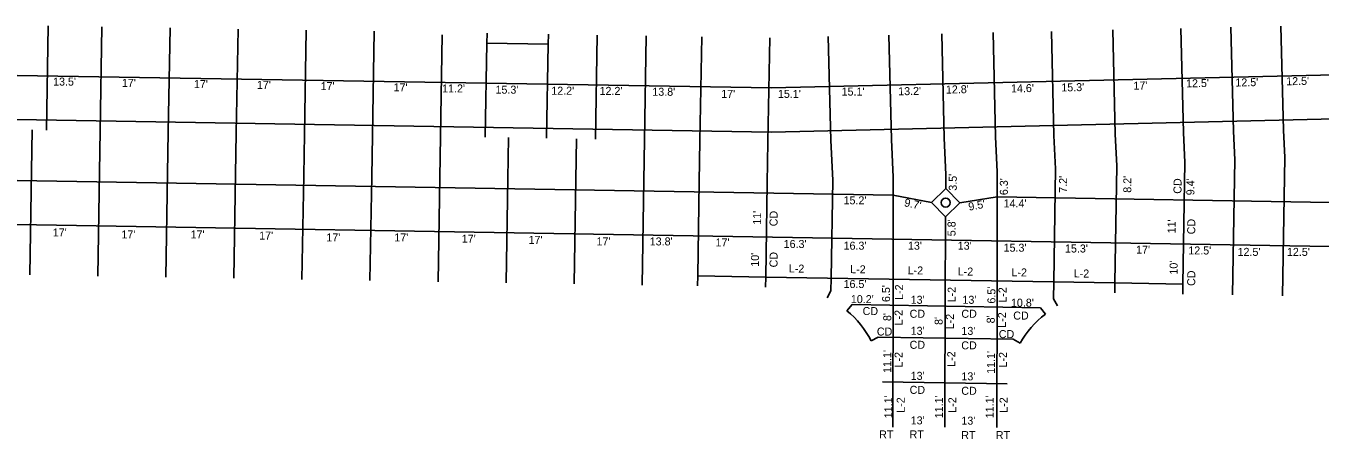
# Model space of a CAD drawing. Extents: x 4995357 to 4999033, y 3881202 to 3881750.
# Drawn here: x 4996458 to 4996781.3, y 3881601.9 to 3881705.1 of the extents above; entities that cross this region are included whole.
import ezdxf

# ---------------------------------------------------------------- set-up
doc = ezdxf.new("R2010")
doc.units = 0
for name, color, linetype in [('dsn3DCenterLine', 7, 'Continuous'), ('dsn3DCurbFormgrade', 7, 'Continuous'), ('dsn3DCurbTop', 7, 'Continuous'), ('dsn3DDNC', 7, 'Continuous'), ('dsn3DExistingPvmtBtm', 7, 'Continuous'), ('dsn3DIntakeWell', 7, 'Continuous')]:
    doc.layers.add(name, color=color, linetype=linetype)

msp = doc.modelspace()

# ---------------------------------------------------------------- linework, layer by layer
at = {"layer": 'dsn3DCurbFormgrade'}
for p, q in [((4996463.52, 3881705.11), (4996463.09, 3881679.11)), ((4996771.53, 3881705.08), (4996772.14, 3881679.09)), ((4996476.98, 3881704.89), (4996476.54, 3881678.89)), ((4996493.97, 3881704.6), (4996493.54, 3881678.61)), ((4996510.97, 3881704.32), (4996510.54, 3881678.33)), ((4996527.97, 3881704.04), (4996527.54, 3881678.04)), ((4996544.97, 3881703.76), (4996544.53, 3881677.76)), ((4996561.95, 3881702.85), (4996561.53, 3881677.48)), ((4996600.3, 3881676.83), (4996600.73, 3881702.83)), ((4996612.96, 3881702.63), (4996612.52, 3881676.63)), ((4996626.8, 3881702.4), (4996626.37, 3881676.4)), ((4996643.8, 3881702.12), (4996643.37, 3881676.12)), ((4996658.44, 3881702.44), (4996659.05, 3881676.45)), ((4996673.58, 3881702.77), (4996674.19, 3881676.78)), ((4996686.79, 3881703.1), (4996687.4, 3881677.11)), ((4996699.62, 3881703.43), (4996700.23, 3881677.44)), ((4996714.19, 3881703.74), (4996714.8, 3881677.75)), ((4996729.51, 3881704.1), (4996730.12, 3881678.11)), ((4996746.55, 3881704.5), (4996747.16, 3881678.51)), ((4996759.04, 3881704.79), (4996759.65, 3881678.8)), ((4996572.74, 3881677.29), (4996573.13, 3881700.79)), ((4996588.07, 3881677.04), (4996588.46, 3881700.53)), ((4996715.22, 3881669.4), (4996714.75, 3881641.18)), ((4996730.52, 3881670.16), (4996730.03, 3881640.92)), ((4996747.53, 3881671.01), (4996747.03, 3881640.64)), ((4996759.45, 3881637.94), (4996760.01, 3881671.64)), ((4996771.91, 3881637.73), (4996772.48, 3881672.26)), ((4996459.38, 3881668.92), (4996458.94, 3881642.93)), ((4996476.37, 3881668.64), (4996475.94, 3881642.65)), ((4996493.37, 3881668.36), (4996492.94, 3881642.36)), ((4996510.37, 3881668.08), (4996509.94, 3881642.08)), ((4996527.37, 3881667.79), (4996526.93, 3881641.8)), ((4996544.36, 3881667.51), (4996543.93, 3881641.52)), ((4996561.36, 3881667.23), (4996560.93, 3881641.23)), ((4996578.36, 3881666.95), (4996577.93, 3881640.95)), ((4996595.36, 3881666.66), (4996594.92, 3881640.67)), ((4996612.35, 3881666.38), (4996611.92, 3881640.39)), ((4996626.2, 3881666.15), (4996625.81, 3881642.66)), ((4996659.54, 3881666.61), (4996659.13, 3881642.1)), ((4996674.66, 3881667.37), (4996674.61, 3881641.85)), ((4996687.82, 3881664.51), (4996687.81, 3881668.03)), ((4996700.66, 3881668.67), (4996700.61, 3881641.41)), ((4996643.2, 3881665.87), (4996642.81, 3881642.37)), ((4996687.68, 3881651.63), (4996687.7, 3881657.44)), ((4996687.61, 3881641.63), (4996687.68, 3881651.63)), ((4996664.37, 3881635.51), (4996711.43, 3881634.73)), ((4996670.93, 3881627.4), (4996704.6, 3881626.84)), ((4996672.01, 3881616.25), (4996703.15, 3881615.74))]:
    msp.add_line(p, q, dxfattribs=at)
at = {"layer": 'dsn3DCurbTop'}
for p, q in [((4996459.38, 3881668.92), (4996459.55, 3881679.17)), ((4996772.48, 3881672.26), (4996772.14, 3881679.09)), ((4996476.37, 3881668.64), (4996476.54, 3881678.89)), ((4996493.37, 3881668.36), (4996493.54, 3881678.61)), ((4996510.54, 3881678.33), (4996510.37, 3881668.08)), ((4996527.37, 3881667.79), (4996527.54, 3881678.04)), ((4996544.53, 3881677.76), (4996544.36, 3881667.51)), ((4996561.36, 3881667.23), (4996561.53, 3881677.48)), ((4996578.36, 3881666.95), (4996578.53, 3881677.2)), ((4996595.36, 3881666.66), (4996595.53, 3881676.91)), ((4996612.35, 3881666.38), (4996612.52, 3881676.63)), ((4996626.37, 3881676.4), (4996626.2, 3881666.15)), ((4996643.2, 3881665.87), (4996643.37, 3881676.12)), ((4996659.54, 3881666.61), (4996659.05, 3881676.45)), ((4996674.66, 3881667.37), (4996674.19, 3881676.78)), ((4996687.81, 3881668.03), (4996687.4, 3881677.11)), ((4996700.66, 3881668.67), (4996700.23, 3881677.44)), ((4996715.22, 3881669.4), (4996714.8, 3881677.75)), ((4996730.52, 3881670.16), (4996730.12, 3881678.11)), ((4996747.53, 3881671.01), (4996747.16, 3881678.51)), ((4996760.01, 3881671.64), (4996759.65, 3881678.8)), ((4996658.19, 3881637.18), (4996659.08, 3881638.97)), ((4996663.08, 3881633.98), (4996664.37, 3881635.51)), ((4996712.66, 3881633.16), (4996711.43, 3881634.73)), ((4996715.67, 3881635.17), (4996714.68, 3881636.91)), ((4996669.16, 3881626.47), (4996670.93, 3881627.4)), ((4996706.34, 3881625.85), (4996704.6, 3881626.84))]:
    msp.add_line(p, q, dxfattribs=at)
at = {"layer": 'dsn3DDNC'}
for p, q in [((4996408.86, 3881693.52), (4996644.25, 3881689.61)), ((4996800.58, 3881693.26), (4996644.25, 3881689.61)), ((4996408.76, 3881682.52), (4996644.28, 3881678.6)), ((4996800.62, 3881682.26), (4996644.28, 3881678.6)), ((4996408.62, 3881667.27), (4996674.65, 3881662.85)), ((4996674.65, 3881662.85), (4996684.23, 3881661.03)), ((4996691.3, 3881660.92), (4996700.65, 3881662.42)), ((4996700.65, 3881662.42), (4997007.04, 3881657.33)), ((4996408.52, 3881656.27), (4997479.7, 3881638.47)), ((4996642.81, 3881642.37), (4996642.76, 3881639.87)), ((4996642.81, 3881642.37), (4996730.03, 3881640.92)), ((4996659.13, 3881642.1), (4996659.08, 3881638.97)), ((4996674.61, 3881641.85), (4996674.53, 3881604.9)), ((4996687.61, 3881641.63), (4996687.53, 3881604.87)), ((4996700.61, 3881641.41), (4996700.53, 3881604.85)), ((4996714.75, 3881641.18), (4996714.68, 3881636.91)), ((4996730.03, 3881640.92), (4996729.99, 3881638.42))]:
    msp.add_line(p, q, dxfattribs=at)
at = {"layer": 'dsn3DExistingPvmtBtm'}
for p, q in [((4996625.77, 3881640.16), (4996625.81, 3881642.66)), ((4996625.81, 3881642.66), (4996642.81, 3881642.37)), ((4996730.03, 3881640.92), (4996747.03, 3881640.64)), ((4996747.03, 3881640.64), (4996746.99, 3881638.14))]:
    msp.add_line(p, q, dxfattribs=at)
msp.add_lwpolyline([(4996573.17, 3881703.29), (4996573.13, 3881700.79), (4996588.46, 3881700.53), (4996588.5, 3881703.03)], dxfattribs=at)
msp.add_lwpolyline([(4996691.3, 3881660.92), (4996687.7, 3881657.44), (4996684.23, 3881661.03), (4996687.82, 3881664.51)], close=True, dxfattribs=at)
msp.add_circle((4996687.76, 3881660.98), 1.12, dxfattribs=at)
at = {"layer": 'dsn3DIntakeWell'}
for points in [[(4996663.08, 3881633.98), (4996664.37, 3881635.51), (4996711.43, 3881634.73), (4996712.66, 3881633.16)], [(4996706.34, 3881625.85), (4996704.6, 3881626.84), (4996670.93, 3881627.4), (4996669.16, 3881626.47)]]:
    msp.add_lwpolyline(points, dxfattribs=at)
for centre, start, end in [((4996647.05, 3881614.8), 27.8305, 50.1058), ((4996728.05, 3881613.45), 127.9907, 150.266)]:
    msp.add_arc(centre, 25, start, end, dxfattribs=at)

# ---------------------------------------------------------------- texts
at = {"layer": 'dsn3DCenterLine'}
for s, p in [("13.5'", (4996464.76, 3881690.2)), ("17'", (4996481.95, 3881689.88)), ("17'", (4996499.95, 3881689.59)), ("17'", (4996515.68, 3881689.39)), ("17'", (4996531.6, 3881689.06)), ("17'", (4996549.83, 3881688.76)), ("11.2'", (4996561.95, 3881688.48)), ("15.3'", (4996575.29, 3881688.18)), ("12.2'", (4996589.23, 3881687.92)), ("12.2'", (4996601.29, 3881687.88)), ("13.8'", (4996614.47, 3881687.66)), ("17'", (4996631.69, 3881687.14)), ("15.1'", (4996645.85, 3881687.14)), ("15.1'", (4996661.76, 3881687.7)), ("15.2'", (4996662.25, 3881660.55)), ("14.4'", (4996702.23, 3881659.79)), ("17'", (4996464.68, 3881652.52)), ("17'", (4996481.83, 3881652.02)), ("17'", (4996499.11, 3881652.02)), ("17'", (4996516.25, 3881651.76)), ("17'", (4996533.03, 3881651.28)), ("17'", (4996550.01, 3881651.28)), ("17'", (4996566.87, 3881650.97)), ("17'", (4996583.55, 3881650.68)), ("17'", (4996600.52, 3881650.29)), ("13.8'", (4996613.82, 3881650.29)), ("17'", (4996630.26, 3881650.03)), ("16.3'", (4996647.28, 3881649.65)), ("16.3'", (4996662.25, 3881649.22)), ("13'", (4996678.34, 3881649.22)), ("13'", (4996690.77, 3881649.22)), ("15.3'", (4996702.23, 3881648.72)), ("15.3'", (4996717.57, 3881648.52)), ("17'", (4996735.34, 3881648.22)), ("12.5'", (4996748.38, 3881648.03)), ("12.5'", (4996760.69, 3881647.67)), ("12.5'", (4996773.02, 3881647.67)), ("16.5'", (4996662.25, 3881639.65)), ("10.2'", (4996664.07, 3881635.87)), ("13'", (4996679.02, 3881635.71)), ("13'", (4996691.95, 3881635.71)), ('CD', (4996667.01, 3881632.9)), ('CD', (4996678.75, 3881632.22)), ('CD', (4996691.68, 3881632.22)), ("10.8'", (4996704.07, 3881634.98)), ('CD', (4996704.64, 3881631.77)), ('CD', (4996670.57, 3881627.78)), ("13'", (4996679.02, 3881627.96)), ("13'", (4996691.69, 3881627.94)), ('CD', (4996701.03, 3881627.14)), ('CD', (4996678.75, 3881624.47)), ('CD', (4996691.66, 3881624.33)), ("13'", (4996679.02, 3881616.72)), ("13'", (4996691.69, 3881616.59)), ('CD', (4996678.75, 3881613.22)), ('CD', (4996691.66, 3881612.98)), ("13'", (4996679.02, 3881605.59)), ("13'", (4996691.69, 3881605.53)), ('RT', (4996671.15, 3881602.09)), ('RT', (4996678.75, 3881602.09)), ('RT', (4996691.66, 3881601.92)), ('RT', (4996700.29, 3881601.92))]:
    msp.add_text(s, height=2, dxfattribs=at).set_placement(p)
for s, rotation, p in [("12.5'", 1.2562, (4996760.16, 3881689.96)), ("12.5'", 1.2562, (4996772.86, 3881690.27)), ("13.2'", 1.2562, (4996675.92, 3881687.77)), ("12.8'", 1.2562, (4996687.84, 3881688.2)), ("14.6'", 1.2562, (4996704.1, 3881688.48)), ("15.3'", 1.2562, (4996716.67, 3881688.72)), ("17'", 1.2562, (4996734.69, 3881689.17)), ("12.5'", 1.2562, (4996747.84, 3881689.74)), ("3.5'", 90, (4996690.54, 3881663.95)), ("6.3'", 90, (4996703.3, 3881662.84)), ("7.2'", 90, (4996718.09, 3881663.44)), ("8.2'", 90, (4996734.14, 3881663.44)), ('CD', 89.5627, (4996746.67, 3881663.18)), ("9.4'", 90, (4996749.9, 3881662.82)), ("9.7'", 348.1723, (4996677.28, 3881660.09)), ("9.5'", 10.2758, (4996693.61, 3881658.95)), ("11'", 90, (4996641.64, 3881655.44)), ('CD', 89.5627, (4996645.75, 3881655.06)), ("5.8'", 90, (4996690.22, 3881652.58)), ("11'", 90, (4996745.22, 3881653.29)), ('CD', 89.5627, (4996750.1, 3881653.05)), ("10'", 90, (4996641.11, 3881644.97)), ('CD', 89.5627, (4996645.75, 3881644.79)), ('L-2', 359.0482, (4996648.56, 3881643.55)), ('L-2', 359.0482, (4996663.89, 3881643.37)), ('L-2', 359.0482, (4996678.25, 3881643.09)), ('L-2', 359.0482, (4996690.75, 3881642.81)), ('L-2', 359.0482, (4996704.19, 3881642.59)), ('L-2', 359.0482, (4996719.73, 3881642.32)), ("10'", 90, (4996745.71, 3881643)), ('CD', 89.5627, (4996750.1, 3881640.16)), ('L-2', 90, (4996677.12, 3881636.68)), ("6.5'", 90, (4996673.86, 3881636.14)), ('L-2', 90, (4996690.26, 3881636.07)), ("6.5'", 90, (4996700.19, 3881635.76)), ('L-2', 90, (4996702.96, 3881635.99)), ('L-2', 90, (4996676.99, 3881630.31)), ("8'", 90, (4996674.16, 3881631.4)), ("8'", 90, (4996687, 3881630.43)), ('L-2', 90, (4996689.82, 3881629.34)), ("8'", 90, (4996700.02, 3881630.82)), ('L-2', 90, (4996702.84, 3881629.73)), ("11.1'", 90, (4996674.16, 3881618.46)), ('L-2', 90, (4996676.99, 3881619.81)), ('L-2', 90, (4996690.15, 3881619.98)), ("11.1'", 90, (4996700.07, 3881618.22)), ('L-2', 90, (4996703.06, 3881619.8)), ("11.1'", 90, (4996674.44, 3881607.13)), ('L-2', 90, (4996677.53, 3881608.5)), ("11.1'", 90, (4996687.08, 3881607.13)), ('L-2', 90, (4996690.43, 3881608.5)), ("11.1'", 90, (4996699.76, 3881607.13)), ('L-2', 90, (4996703.23, 3881608.5))]:
    msp.add_text(s, height=2, rotation=rotation, dxfattribs=at).set_placement(p)

doc.saveas('drawing.dxf')
